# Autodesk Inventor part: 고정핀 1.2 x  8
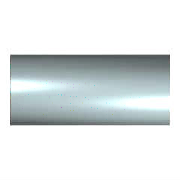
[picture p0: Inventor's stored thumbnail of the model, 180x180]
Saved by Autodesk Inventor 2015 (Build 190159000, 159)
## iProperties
IsCustomPart: 1
Created: 2012-02
Part Number: 고정핀 1.2 x  8
Material: 강철, 연강
Description: 평행 핀
Document SubType Name: Modeling
Standard: KS B 1320
Designer: P15F
Standards Organization: KS
Language: ko-KR
Size Designation: C 1.2 x  8
Categories: <MemberInstance><Categories><Category DisplayName="조임쇠" InternalName="e4da775c-781d-43d5-af7c-5136215cf5a6" Mnemonic="FSTN"><Category DisplayName="핀" InternalNa
Density: 1 g/cm^3
Appearance: 노란색
Author: P15F
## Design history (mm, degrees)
sketch "스케치1"
  geometry: C1 r 0.6 at (0, 0); 1 further point
  constraints: 1 centre point, 1 coincident
  dimensions: "d1" = 1.2 diameter of C1 (= NND)
extrude "본체" new body sketch "스케치1" distance "d2" = 8 (= NLG); taper "d3" = 0 deg
node "작업 평면1"
node "작업 평면2"
body "Solid1"
other parameters: "NND" = 1.2 [user parameter; used in 1 equation term], "NLG" = 8 [user parameter; used in 1 equation term], "d8" = 0, "d9" = 0, "d10" = 0
